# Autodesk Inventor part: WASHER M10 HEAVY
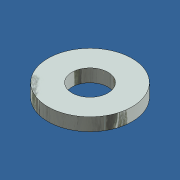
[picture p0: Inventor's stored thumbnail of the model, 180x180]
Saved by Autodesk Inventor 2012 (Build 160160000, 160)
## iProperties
Created: 2013-10
Part Number: WASHER M10 HEAVY
Material: Steel
Document SubType Name: Modeling
Designer: Admin
Density: 7.85 g/cm^3
Mass: 11.3289 g
Surface Area: 11.8202 cm^2
Volume: 1.44317 cm^3
Description: WASHER M10 HEAVY
Author: Admin
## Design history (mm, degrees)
sketch "Sketch1"
  geometry: C1 r 5.25 at (0, 0); C2 r 12.25 at (0, 0); 1 further point
  constraints: 2 centre point, 2 coincident
  dimensions: "d0" = 10.5 diameter of C1; "d1" = 24.5 diameter of C2
extrude "Extrusion1" new body sketch "Sketch1" distance "d2" = 3.75; taper "d3" = 0 deg
body "Solid1"
